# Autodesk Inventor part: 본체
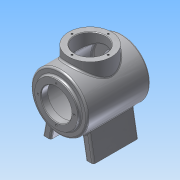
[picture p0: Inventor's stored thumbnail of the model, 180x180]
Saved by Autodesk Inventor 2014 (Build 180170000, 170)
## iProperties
Created: 2015-01
Part Number: 본체
Material: 알루미늄 6061
Document SubType Name: Modeling
Designer: user
Density: 2.71 g/cm^3
Appearance: 알루미늄 - 평지
Mass: 1007 g
Surface Area: 1053.24 cm^2
Volume: 371.588 cm^3
Author: user
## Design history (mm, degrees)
sketch "스케치1"
  geometry: C1 r 50 at (0, 0); C2 r 38 at (0, 0); 1 further point
  constraints: 2 centre point, 1 coincident, 1 concentric
  dimensions: "d0" = 76 diameter of C2; "d1" = 100 diameter of C1
extrude "돌출1" new body sketch "스케치1" stored distance "d2" = 112; taper "d3" = 0 deg
extrude "돌출2" join sketch "스케치1" stored distance "d4" = 122; taper "d5" = 0 deg
sketch "스케치2" dims "d6" = 64
  geometry: 3 further points
  constraints: 2 vertical alignment, 1 coincident, 2 other
hole "구멍1" sketch "스케치2" at (0, 32) diameter "d7" = 3.242; stored, may be unused: countersink angle "d11" = 90 deg, drill point angle "d13" = 118 deg; dims "d8" = 8, "d9" = 4, "d10" = 2, "d12" = 10
hole "구멍2" diameter "d19" = 54; stored, may be unused: countersink angle "d23" = 90 deg, drill point angle "d25" = 0 deg; dims "d17" = 10, "d18" = 10, "d20" = 8, "d21" = 4, "d22" = 2, "d24" = 12
hole "구멍3" diameter "d28" = 90; stored, may be unused: countersink angle "d32" = 90 deg, drill point angle "d34" = 0 deg; dims "d26" = 10, "d27" = 10, "d29" = 8, "d30" = 4, "d31" = 2, "d33" = 97
hole "구멍4" diameter "d37" = 54; stored, may be unused: countersink angle "d41" = 90 deg, drill point angle "d43" = 0 deg; dims "d35" = 10, "d36" = 10, "d38" = 8, "d39" = 4, "d40" = 2, "d42" = 13
sketch "스케치3"
  geometry: L1 (30.878, -80)-(44.878, -80); L2 (44.878, -80)-(36.75, -33.903); L3 (30.878, -80)-(24.462, -43.608); L4 (-36.75, -33.903)-(-44.878, -80); L5 (-44.878, -80)-(-30.878, -80); L6 (-30.878, -80)-(-24.462, -43.608); A1 r 50 centre (0, 0) between (36.75, -33.903) and (24.462, -43.608) reference; 1 further point
  constraints: 12 end point, 4 point on circle, 3 equal length, 2 collinear, 2 parallel, 1 horizontal, 1 horizontal alignment
  dimensions: "d44" = 80 distance from line of point (0, 0) L1; "d45" = 14 distance of L1.start L1.end; "d46" = 100 deg angle of L1 L2
extrude "돌출3" join sketch "스케치3" stored distance "d47" = 80; taper "d48" = 0 deg
node "작업 평면1"
sketch "스케치4"
  geometry: L1 (-82.878, -101)-(-6.878, -101) reference; C1 r 38 at (-44.878, -39); 2 further points
  constraints: 1 centre point, 1 midpoint, 1 vertical alignment
  dimensions: "d50" = 76 diameter of C1; "d51" = 62 distance from line of C1.centre L1
extrude "돌출4" join sketch "스케치4" stored distance "d52" = 80; taper "d53" = 0 deg
sketch "스케치5" dims "d54" = 64
  geometry: C1 r 38 at (0, 0) reference; 3 further points
  constraints: 2 vertical alignment, 3 other
hole "구멍5" sketch "스케치5" at (0, 32) diameter "d55" = 3.242; stored, may be unused: countersink angle "d59" = 90 deg, drill point angle "d61" = 118 deg; dims "d56" = 8, "d57" = 4, "d58" = 2, "d60" = 10
node "작업축1"
node "작업 평면3"
  node "작업 평면2"
sketch "스케치6"
  geometry: L1 (-6, 28)-(6, 28); L2 (6, 28)-(6, -26); L3 (6, -26)-(-6, -26); L4 (-6, -26)-(-6, 28); L5 (-62, -37)-(-62, 39) reference; L6 (-38, -61)-(38, -61) reference; 5 further points
  constraints: 8 end point, 4 midpoint, 2 parallel, 1 horizontal, 1 horizontal alignment, 1 perpendicular, 1 vertical alignment
  dimensions: "d66" = 54 distance of L1.end L2.end; "d67" = 12 distance of L2.end L3.end
extrude "돌출5" join sketch "스케치6" stored distance "d68" = 80; taper "d69" = 0 deg
sketch "스케치7"
  geometry: L1 (-26, 6)-(28, 6) reference; L2 (28, 6)-(28, -6) reference; 4 further points
  constraints: 2 midpoint, 1 horizontal alignment, 1 vertical alignment, 1 other
feature "엠보싱1" sketch "스케치7" dims "d24" = 12, "d70" = 0.5, "d71" = 0
hole "구멍6" diameter "d74" = 54; stored, may be unused: countersink angle "d78" = 90 deg, drill point angle "d80" = 0 deg; dims "d72" = 10, "d73" = 10, "d75" = 8, "d76" = 4, "d77" = 2, "d79" = 10
chamfer "모따기1" distance "d81" = 1; stored, may be unused: second distance "d82" = 2, angle "d83" = 45 deg
fillet "모깎기1" dims "d84" = 3
fillet "모깎기2" dims "d85" = 3
fillet "모깎기3" dims "d86" = 3
node "솔리드1"
pattern_circular "원형 패턴1" dims angle "d15" = 360 deg
mirror "대칭1"
pattern_circular "원형 패턴2" dims angle "d63" = 360 deg
other parameters: "d49" = -142, "d65" = -2
